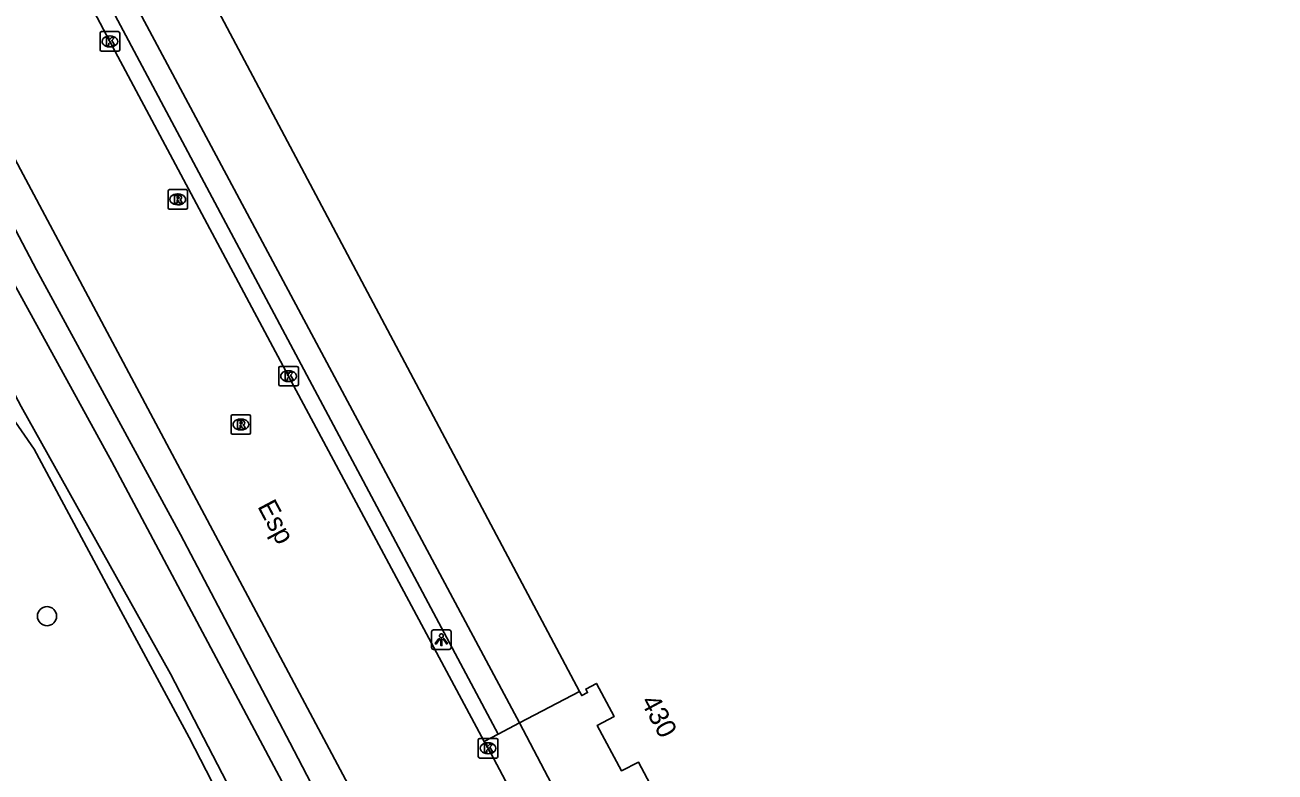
# Model space of a CAD drawing. Extents: x 161389 to 162585, y 388479 to 389761.
# Drawn here: x 161966 to 162029.9, y 388898.4 to 388936.6 of the extents above; entities that cross this region are included whole.
import ezdxf

# ---------------------------------------------------------------- set-up
doc = ezdxf.new("R2010")
doc.units = 0
for name, color, linetype in [('IMGEO_Berm_groen', 7, 'Continuous'), ('IMGEO_Boom', 7, 'Continuous'), ('IMGEO_Kolk', 7, 'Continuous'), ('IMGEO_Lichtpunt', 7, 'Continuous'), ('IMGEO_Openbare_ruimte_label', 7, 'Continuous'), ('IMGEO_Pand', 7, 'Continuous'), ('IMGEO_Pand_nummerreeks', 7, 'Continuous'), ('IMGEO_Rijbaan_lokaal_gesloten', 7, 'Continuous'), ('IMGEO_Rioolput', 7, 'Continuous'), ('IMGEO_Voetpad_open', 7, 'Continuous'), ('IMGEO_Waterloop', 7, 'Continuous')]:
    doc.layers.add(name, color=color, linetype=linetype)

msp = doc.modelspace()

# ---------------------------------------------------------------- linework, layer by layer
at = {"layer": 'IMGEO_Berm_groen'}
for points in [[(161999.373, 388861.434), (161996.577, 388867.59), (161994.36, 388871.666), (161991.934, 388876.857), (161989.458, 388881.111), (161985.375, 388888.699), (161979.556, 388899.869), (161973.975, 388910.518), (161966.605, 388924.048), (161961.038, 388934.61)], [(161964.669, 388917.476), (161966.487, 388914.871), (161970.685, 388907.05), (161974.403, 388900.125), (161979.081, 388891.053), (161983.254, 388883.681), (161986.387, 388877.47), (161989.966, 388870.547), (161993.502, 388862.945)]]:
    msp.add_lwpolyline(points, dxfattribs=at)
at = {"layer": 'IMGEO_Boom'}
msp.add_circle((161967.141, 388906.331), 0.489, dxfattribs=at)
at = {"layer": 'IMGEO_Kolk'}
for p, q in [((161969.857, 388935.312), (161969.857, 388936.164)), ((161969.932, 388936.238), (161970.784, 388936.238)), ((161970.345, 388936.018), (161970.37, 388936.018)), ((161970.858, 388936.164), (161970.858, 388935.312)), ((161970.368, 388935.458), (161970.343, 388935.458)), ((161970.784, 388935.238), (161969.932, 388935.238)), ((161978.992, 388918.186), (161978.992, 388919.038)), ((161979.067, 388919.112), (161979.919, 388919.112)), ((161979.48, 388918.892), (161979.505, 388918.892)), ((161979.993, 388919.038), (161979.993, 388918.186)), ((161979.919, 388918.112), (161979.067, 388918.112)), ((161979.503, 388918.332), (161979.478, 388918.332)), ((161989.192, 388899.146), (161989.192, 388899.998)), ((161989.267, 388900.072), (161990.119, 388900.072)), ((161989.68, 388899.852), (161989.705, 388899.852)), ((161990.193, 388899.998), (161990.193, 388899.146)), ((161990.119, 388899.072), (161989.267, 388899.072)), ((161989.703, 388899.292), (161989.678, 388899.292))]:
    msp.add_line(p, q, dxfattribs=at)
for points in [[(161969.857, 388935.312), (161969.857, 388936.164)], [(161969.932, 388936.238), (161970.784, 388936.238)], [(161970.858, 388936.164), (161970.858, 388935.312)], [(161970.178, 388935.938), (161970.301, 388935.938), (161970.301, 388935.787), (161970.431, 388935.938), (161970.595, 388935.938), (161970.449, 388935.787), (161970.602, 388935.538), (161970.45, 388935.538), (161970.365, 388935.702), (161970.301, 388935.635), (161970.301, 388935.538), (161970.178, 388935.538), (161970.178, 388935.938)], [(161970.784, 388935.238), (161969.932, 388935.238)], [(161978.992, 388918.186), (161978.992, 388919.038)], [(161979.067, 388919.112), (161979.919, 388919.112)], [(161979.313, 388918.812), (161979.436, 388918.812), (161979.436, 388918.661), (161979.566, 388918.812), (161979.73, 388918.812), (161979.584, 388918.661), (161979.737, 388918.412), (161979.585, 388918.412), (161979.5, 388918.576), (161979.436, 388918.509), (161979.436, 388918.412), (161979.313, 388918.412), (161979.313, 388918.812)], [(161979.993, 388919.038), (161979.993, 388918.186)], [(161979.919, 388918.112), (161979.067, 388918.112)], [(161989.192, 388899.146), (161989.192, 388899.998)], [(161989.267, 388900.072), (161990.119, 388900.072)], [(161989.513, 388899.772), (161989.636, 388899.772), (161989.636, 388899.621), (161989.766, 388899.772), (161989.93, 388899.772), (161989.784, 388899.621), (161989.937, 388899.372), (161989.785, 388899.372), (161989.7, 388899.536), (161989.636, 388899.469), (161989.636, 388899.372), (161989.513, 388899.372), (161989.513, 388899.772)], [(161990.193, 388899.998), (161990.193, 388899.146)], [(161990.119, 388899.072), (161989.267, 388899.072)]]:
    msp.add_lwpolyline(points, dxfattribs=at)
for centre, start, end in [((161969.934, 388936.162), 91.55205, 178.44795), ((161969.934, 388936.162), 91.55205, 178.44795), ((161970.782, 388936.162), 1.55205, 88.44795), ((161970.782, 388936.162), 1.55205, 88.44795), ((161969.934, 388935.314), 181.55205, 268.44795), ((161969.934, 388935.314), 181.55205, 268.44795), ((161970.782, 388935.314), 271.55205, 358.44795), ((161970.782, 388935.314), 271.55205, 358.44795), ((161979.069, 388919.036), 91.55205, 178.44795), ((161979.069, 388919.036), 91.55205, 178.44795), ((161979.917, 388919.036), 1.55205, 88.44795), ((161979.917, 388919.036), 1.55205, 88.44795), ((161979.069, 388918.188), 181.55205, 268.44795), ((161979.069, 388918.188), 181.55205, 268.44795), ((161979.917, 388918.188), 271.55205, 358.44795), ((161979.917, 388918.188), 271.55205, 358.44795), ((161989.269, 388899.996), 91.55205, 178.44795), ((161989.269, 388899.996), 91.55205, 178.44795), ((161990.117, 388899.996), 1.55205, 88.44795), ((161990.117, 388899.996), 1.55205, 88.44795), ((161989.269, 388899.148), 181.55205, 268.44795), ((161989.269, 388899.148), 181.55205, 268.44795), ((161990.117, 388899.148), 271.55205, 358.44795), ((161990.117, 388899.148), 271.55205, 358.44795)]:
    msp.add_arc(centre, 0.0765, start, end, dxfattribs=at)
for centre, major_axis, ratio, start_param, end_param in [((161970.344, 388935.738), (-0.387, 0.002), 0.722429, 4.712389, 7.853982), ((161970.369, 388935.738), (-0.39, 0.002), 0.717154, 1.570796, 4.712389), ((161979.479, 388918.612), (-0.387, 0.002), 0.722429, 4.712389, 7.853982), ((161979.504, 388918.612), (-0.39, 0.002), 0.717154, 1.570796, 4.712389), ((161989.679, 388899.572), (-0.387, 0.002), 0.722429, 4.712389, 7.853982), ((161989.704, 388899.572), (-0.39, 0.002), 0.717154, 1.570796, 4.712389)]:
    msp.add_ellipse(centre, major_axis=major_axis, ratio=ratio, start_param=start_param, end_param=end_param, dxfattribs=at)
at = {"layer": 'IMGEO_Lichtpunt'}
for p, q in [((161986.809, 388905.53), (161986.809, 388904.723)), ((161986.809, 388905.53), (161986.809, 388904.723)), ((161987.711, 388905.625), (161986.903, 388905.625)), ((161987.711, 388905.625), (161986.903, 388905.625)), ((161987.805, 388904.723), (161987.805, 388905.53)), ((161987.805, 388904.723), (161987.805, 388905.53)), ((161986.903, 388904.629), (161987.711, 388904.629)), ((161986.903, 388904.629), (161987.711, 388904.629))]:
    msp.add_line(p, q, dxfattribs=at)
for points in [[(161987.183, 388905.194), (161987.222, 388905.166), (161987.034, 388904.904), (161986.996, 388904.931), (161987.183, 388905.194)], [(161987.285, 388905.146), (161987.332, 388905.146), (161987.332, 388904.824), (161987.285, 388904.824), (161987.285, 388905.146)], [(161987.395, 388905.166), (161987.433, 388905.193), (161987.62, 388904.931), (161987.581, 388904.903), (161987.395, 388905.166)]]:
    msp.add_lwpolyline(points, dxfattribs=at)
msp.add_circle((161987.308, 388905.328), 0.0994, dxfattribs=at)
for centre, start, end in [((161986.903, 388905.53), 90, 180), ((161986.903, 388905.53), 90, 180), ((161987.711, 388905.53), 0, 90), ((161987.711, 388905.53), 0, 90), ((161986.903, 388904.723), 180, 270), ((161986.903, 388904.723), 180, 270), ((161987.711, 388904.723), 270, 0), ((161987.711, 388904.723), 270, 360)]:
    msp.add_arc(centre, 0.0946, start, end, dxfattribs=at)
at = {"layer": 'IMGEO_Pand'}
for points in [[(161973.132, 388942.524), (161994.377, 388902.481)], [(161994.377, 388902.481), (161994.489, 388902.269), (161994.781, 388902.424), (161994.687, 388902.601), (161995.235, 388902.891), (161996.136, 388901.195), (161995.281, 388900.739), (161996.517, 388898.421), (161997.381, 388898.862), (161998.275, 388897.186), (161997.728, 388896.895), (161997.634, 388897.072), (161997.395, 388896.945), (161997.547, 388896.655)]]:
    msp.add_lwpolyline(points, dxfattribs=at)
at = {"layer": 'IMGEO_Rijbaan_lokaal_gesloten'}
for points in [[(161968.389, 388939.475), (161970.358, 388935.737), (161979.492, 388918.612), (161989.503, 388899.925)], [(161961.889, 388936.482), (161995.294, 388873.775), (161997.09, 388870.182), (161997.535, 388869.23), (162000, 388863.953)], [(161992.639, 388894.058), (161989.692, 388899.572), (161989.503, 388899.925)]]:
    msp.add_lwpolyline(points, dxfattribs=at)
at = {"layer": 'IMGEO_Rioolput'}
for p, q in [((161973.328, 388927.23), (161973.328, 388928.082)), ((161973.403, 388928.156), (161974.255, 388928.156)), ((161973.816, 388927.936), (161973.841, 388927.936)), ((161974.329, 388928.082), (161974.329, 388927.23)), ((161974.255, 388927.156), (161973.403, 388927.156)), ((161973.839, 388927.376), (161973.814, 388927.376)), ((161976.553, 388915.712), (161976.553, 388916.564)), ((161976.628, 388916.638), (161977.48, 388916.638)), ((161977.041, 388916.418), (161977.066, 388916.418)), ((161977.554, 388916.564), (161977.554, 388915.712)), ((161977.48, 388915.638), (161976.628, 388915.638)), ((161977.064, 388915.858), (161977.039, 388915.858))]:
    msp.add_line(p, q, dxfattribs=at)
for points in [[(161973.328, 388927.23), (161973.328, 388928.082)], [(161973.403, 388928.156), (161974.255, 388928.156)], [(161973.917, 388927.854), (161973.665, 388927.856), (161973.665, 388927.456)], [(161973.843, 388927.775), (161973.789, 388927.775), (161973.789, 388927.694)], [(161973.789, 388927.694), (161973.841, 388927.694)], [(161974.329, 388928.082), (161974.329, 388927.23)], [(161974.255, 388927.156), (161973.403, 388927.156)], [(161973.665, 388927.456), (161973.789, 388927.456), (161973.789, 388927.618), (161973.8, 388927.618)], [(161973.847, 388927.589), (161973.918, 388927.456), (161974.058, 388927.456), (161973.993, 388927.582)], [(161976.553, 388915.712), (161976.553, 388916.564)], [(161976.628, 388916.638), (161977.48, 388916.638)], [(161977.142, 388916.336), (161976.89, 388916.338), (161976.89, 388915.938)], [(161977.068, 388916.257), (161977.014, 388916.257), (161977.014, 388916.176)], [(161977.014, 388916.176), (161977.066, 388916.176)], [(161977.554, 388916.564), (161977.554, 388915.712)], [(161977.48, 388915.638), (161976.628, 388915.638)], [(161976.89, 388915.938), (161977.014, 388915.938), (161977.014, 388916.1), (161977.025, 388916.1)], [(161977.072, 388916.071), (161977.143, 388915.938), (161977.283, 388915.938), (161977.218, 388916.064)]]:
    msp.add_lwpolyline(points, dxfattribs=at)
for centre, radius, start, end in [((161973.405, 388928.08), 0.0765, 91.55205, 178.44795), ((161973.405, 388928.08), 0.0765, 91.55205, 178.44795), ((161973.825, 388927.883), 0.19, 274.7715, 282.96867), ((161973.849, 388927.679), 0.0964, 77.00612, 93.18647), ((161973.863, 388927.736), 0.0378, 276.66336, 79.67722), ((161973.916, 388927.744), 0.109, 350.36119, 89.41601), ((161973.914, 388927.744), 0.112, 277.58423, 350.98172), ((161974.253, 388928.08), 0.0765, 1.55205, 88.44795), ((161974.253, 388928.08), 0.0765, 1.55205, 88.44795), ((161973.405, 388927.232), 0.0765, 181.55205, 268.44795), ((161973.405, 388927.232), 0.0765, 181.55205, 268.44795), ((161973.799, 388927.565), 0.0533, 26.02933, 88.69889), ((161973.898, 388927.529), 0.108, 29.51342, 73.79051), ((161974.253, 388927.232), 0.0765, 271.55205, 358.44795), ((161974.253, 388927.232), 0.0765, 271.55205, 358.44795), ((161976.63, 388916.562), 0.0765, 91.55205, 178.44795), ((161976.63, 388916.562), 0.0765, 91.55205, 178.44795), ((161977.05, 388916.365), 0.19, 274.7715, 282.96867), ((161977.074, 388916.161), 0.0964, 77.00612, 93.18647), ((161977.088, 388916.218), 0.0378, 276.66336, 79.67722), ((161977.141, 388916.226), 0.109, 350.36119, 89.41601), ((161977.139, 388916.226), 0.112, 277.58423, 350.98172), ((161977.478, 388916.562), 0.0765, 1.55205, 88.44795), ((161977.478, 388916.562), 0.0765, 1.55205, 88.44795), ((161976.63, 388915.714), 0.0765, 181.55205, 268.44795), ((161976.63, 388915.714), 0.0765, 181.55205, 268.44795), ((161977.024, 388916.047), 0.0533, 26.02933, 88.69889), ((161977.123, 388916.011), 0.108, 29.51342, 73.79051), ((161977.478, 388915.714), 0.0765, 271.55205, 358.44795), ((161977.478, 388915.714), 0.0765, 271.55205, 358.44795)]:
    msp.add_arc(centre, radius, start, end, dxfattribs=at)
for centre, major_axis, ratio, start_param, end_param in [((161973.815, 388927.656), (-0.387, 0.002), 0.722429, 4.712389, 7.853982), ((161973.84, 388927.656), (-0.39, 0.002), 0.717154, 1.570796, 4.712389), ((161977.04, 388916.138), (-0.387, 0.002), 0.722429, 4.712389, 7.853982), ((161977.065, 388916.138), (-0.39, 0.002), 0.717154, 1.570796, 4.712389)]:
    msp.add_ellipse(centre, major_axis=major_axis, ratio=ratio, start_param=start_param, end_param=end_param, dxfattribs=at)
at = {"layer": 'IMGEO_Voetpad_open'}
for points in [[(161970.155, 388940.477), (161991.298, 388900.866)], [(161990.206, 388900.294), (161969.102, 388939.923)], [(161991.298, 388900.866), (161994.377, 388902.481)], [(161991.298, 388900.866), (161990.206, 388900.294)], [(161994.39, 388894.985), (161991.298, 388900.866)], [(161989.503, 388899.925), (161990.206, 388900.294)]]:
    msp.add_lwpolyline(points, dxfattribs=at)
at = {"layer": 'IMGEO_Waterloop'}
for points in [[(161945.748, 388964.741), (161945.568, 388964.712), (161945.094, 388964.318), (161945.013, 388963.297), (161945.528, 388962.107), (161945.974, 388961.502), (161946.442, 388961.06), (161947.301, 388960.849), (161947.986, 388960.564), (161948.315, 388960.758), (161948.723, 388960.021), (161948.43, 388959.76), (161948.106, 388958.987), (161947.764, 388958.501), (161947.715, 388957.621), (161949.215, 388953.942), (161950.142, 388952.44), (161956.024, 388940.834), (161962.678, 388928.366), (161970.452, 388914.234), (161989.402, 388878.601), (161994.658, 388868.229), (161999.307, 388858.055)], [(161941.837, 388963.119), (161942.447, 388962.063), (161943.053, 388960.238), (161945.813, 388954.71), (161955.4, 388937.311), (161959.219, 388929.478), (161965.825, 388917.051), (161973.46, 388903.38), (161979.241, 388892.222), (161985.653, 388880.171), (161992.962, 388865.623), (161997.026, 388856.73), (162011.729, 388825.521), (162017.299, 388813.29), (162022.898, 388799.997), (162028.09, 388786.865), (162028.763, 388785.061), (162029.937, 388781.916)]]:
    msp.add_lwpolyline(points, dxfattribs=at)

# ---------------------------------------------------------------- texts
at = {"layer": 'IMGEO_Openbare_ruimte_label'}
msp.add_text('Esp', height=1, rotation=298.02532, dxfattribs=at).set_placement((161977.881, 388911.949))
at = {"layer": 'IMGEO_Pand_nummerreeks'}
msp.add_text('430', height=1, rotation=298.06899, dxfattribs=at).set_placement((161997.477, 388901.976))

doc.saveas('drawing.dxf')
